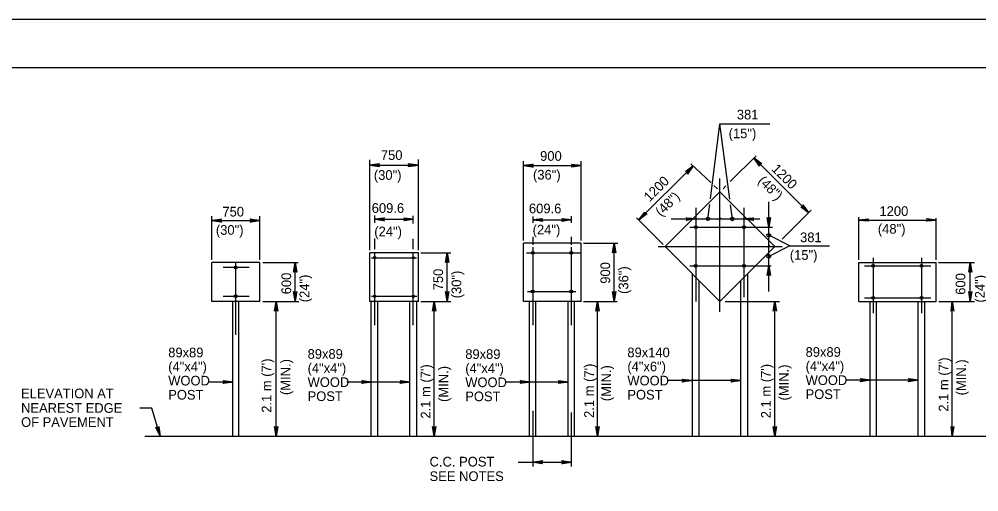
# Model space of a CAD drawing. Extents: x 649454 to 651200, y 295188 to 295782.
# Drawn here: x 649864.6 to 650161.4, y 295635.3 to 295781.6 of the extents above; entities that cross this region are included whole.
import ezdxf

# ---------------------------------------------------------------- set-up
doc = ezdxf.new("R2010")
doc.units = 0
for name, color, linetype in [('1', 7, 'Continuous'), ('2', 7, 'Continuous'), ('3', 7, 'Continuous'), ('PLT-BNDY', 7, 'Continuous')]:
    doc.layers.add(name, color=color, linetype=linetype)

msp = doc.modelspace()

# ---------------------------------------------------------------- linework, layer by layer
at = {"layer": '1'}
msp.add_line((649494.31, 295766.63), (650280.31, 295766.63), dxfattribs=at)
at = {"layer": '2'}
for p, q in [((650078.41, 295726.02), (650081.31, 295749.2)), ((650081.31, 295749.2), (650096.78, 295749.2)), ((649973.06, 295710.12), (649973.06, 295738.04)), ((649988.06, 295710.12), (649988.06, 295738.17)), ((650020.56, 295713.12), (650020.56, 295737.65)), ((650038.44, 295713.12), (650038.44, 295737.65)), ((650092.54, 295739.36), (650084.5, 295731.31)), ((650108.71, 295721.77), (650091.84, 295738.65)), ((649973.06, 295736.42), (649988.06, 295736.42)), ((650020.56, 295736.27), (650038.44, 295736.27)), ((650056.21, 295719.47), (650073.04, 295736.17)), ((650072.33, 295736.88), (650078.54, 295731.03)), ((650081.31, 295691), (650081.31, 295732.31)), ((650079.5, 295730.12), (650080.56, 295729.12)), ((650083.2, 295730.01), (650082.31, 295729.12)), ((650064.44, 295711.25), (650081.31, 295728.12)), ((650098.31, 295711.25), (650081.31, 295728.12)), ((650073.94, 295694.25), (650073.94, 295723.25)), ((650077.64, 295719.81), (650078.19, 295724.23)), ((650088.81, 295695.5), (650088.81, 295723.25)), ((650096.44, 295711.07), (650096.44, 295725.05)), ((649924.19, 295707.12), (649924.19, 295720.64)), ((649939.06, 295707.12), (649939.06, 295720.64)), ((649974.56, 295718.59), (649974.56, 295720.84)), ((649986.44, 295718.37), (649986.44, 295720.77)), ((650023.56, 295718.59), (650023.56, 295720.51)), ((650035.44, 295718.59), (650035.44, 295720.64)), ((650063.81, 295711.87), (650055.55, 295720.13)), ((650081.06, 295719.37), (650081.69, 295720.12)), ((650109.55, 295722.52), (650100.57, 295713.54)), ((650124.31, 295707.12), (650124.31, 295720.3)), ((650148.19, 295707.12), (650148.19, 295720.05)), ((649924.19, 295719.27), (649939.06, 295719.27)), ((649974.56, 295719.65), (649986.44, 295719.65)), ((650023.56, 295719.51), (650035.44, 295719.51)), ((650066.22, 295719.75), (650081.31, 295719.75)), ((650072.06, 295717.25), (650097.56, 295717.25)), ((650081.31, 295719.75), (650093.7, 295719.75)), ((650124.31, 295719.42), (650148.19, 295719.42)), ((650023.56, 295711.75), (650023.56, 295714.2)), ((650035.44, 295711.75), (650035.44, 295714.2)), ((650103.01, 295711.43), (650096.44, 295714.7)), ((649974.56, 295710.37), (649974.56, 295713.75)), ((649986.44, 295710.37), (649986.44, 295713.64)), ((650020.56, 295694.25), (650020.56, 295712.25)), ((650038.44, 295712.25), (650020.56, 295712.25)), ((650023.56, 295686.87), (650023.56, 295711)), ((650035.44, 295686.87), (650035.44, 295711)), ((650038.44, 295694.25), (650038.44, 295712.25)), ((650039.19, 295712.25), (650049.72, 295712.25)), ((650048.59, 295694.25), (650048.59, 295712.25)), ((650062.19, 295711.25), (650100.56, 295711.25)), ((650081.31, 295694.25), (650064.44, 295711.25)), ((650081.31, 295694.25), (650098.31, 295711.25)), ((650096.11, 295710.97), (650096.86, 295711.59)), ((650103.01, 295711.43), (650096.44, 295708.18)), ((650096.44, 295697.3), (650096.44, 295711.07)), ((650103.01, 295711.43), (650115.25, 295711.43)), ((649973.06, 295694.25), (649973.06, 295709.25)), ((649988.06, 295709.25), (649973.06, 295709.25)), ((649974.56, 295686.87), (649974.56, 295709.5)), ((649986.44, 295686.87), (649986.44, 295709.5)), ((649988.06, 295694.25), (649988.06, 295709.25)), ((649988.81, 295709.25), (649998.09, 295709.25)), ((649996.96, 295694.25), (649996.96, 295709.25)), ((650021.56, 295709.25), (650038.06, 295709.25)), ((650023.44, 295709.25), (650023.44, 295709.25)), ((650035.44, 295709.25), (650035.44, 295709.25)), ((649924.19, 295694.25), (649924.19, 295706.25)), ((649939.06, 295706.25), (649924.19, 295706.25)), ((649931.56, 295683.87), (649931.56, 295706.5)), ((649939.06, 295694.25), (649939.06, 295706.25)), ((649939.94, 295706.25), (649950.91, 295706.25)), ((649949.97, 295694.25), (649949.97, 295706.25)), ((649973.56, 295707.75), (649987.44, 295707.75)), ((649974.56, 295707.75), (649974.56, 295707.75)), ((649986.44, 295707.75), (649986.44, 295707.75)), ((650072.06, 295705.25), (650097.23, 295705.25)), ((650124.31, 295694.25), (650124.31, 295706.25)), ((650124.31, 295706.25), (650148.19, 295706.25)), ((650126.06, 295705.25), (650146.56, 295705.25)), ((650128.81, 295690.62), (650128.81, 295707.75)), ((650128.81, 295705.25), (650128.81, 295705.25)), ((650143.81, 295690.62), (650143.81, 295707.75)), ((650143.81, 295705.25), (650143.81, 295705.25)), ((650148.19, 295694.25), (650148.19, 295706.25)), ((650148.94, 295706.25), (650160.08, 295706.25)), ((650149.06, 295706.25), (650154.31, 295706.25)), ((650158.72, 295694.25), (650158.72, 295706.25)), ((649927.69, 295704.87), (649935.69, 295704.87)), ((649931.56, 295704.87), (649931.56, 295704.87)), ((650072.81, 295652.5), (650072.81, 295702.75)), ((650089.94, 295652.5), (650089.94, 295702.75)), ((650074.94, 295652.5), (650074.94, 295700.75)), ((650087.81, 295652.5), (650087.81, 295700.75)), ((650021.81, 295697.25), (650036.81, 295697.25)), ((650022.81, 295697.25), (650022.81, 295697.25)), ((650035.31, 295697.25), (650035.31, 295697.25)), ((649939.06, 295694.25), (649924.19, 295694.25)), ((649927.69, 295695.87), (649935.69, 295695.87)), ((649930.69, 295652.5), (649930.69, 295694.25)), ((649931.56, 295695.87), (649931.56, 295695.87)), ((649932.56, 295652.5), (649932.56, 295694.25)), ((649939.94, 295694.25), (649951.1, 295694.25)), ((649944.06, 295652.5), (649944.06, 295694.25)), ((649988.06, 295694.25), (649973.06, 295694.25)), ((649973.44, 295652.5), (649973.44, 295694.25)), ((649973.56, 295695.87), (649987.56, 295695.87)), ((649974.56, 295695.87), (649974.56, 295695.87)), ((649975.56, 295652.5), (649975.56, 295694.25)), ((649985.44, 295652.5), (649985.44, 295694.25)), ((649986.44, 295695.87), (649986.44, 295695.87)), ((649987.56, 295652.5), (649987.56, 295694.25)), ((649988.81, 295694.25), (649998.09, 295694.25)), ((649992.94, 295652.5), (649992.94, 295694.25)), ((650038.44, 295694.25), (650020.56, 295694.25)), ((650022.44, 295652.5), (650022.44, 295694.25)), ((650024.44, 295652.5), (650024.44, 295694.25)), ((650034.44, 295652.5), (650034.44, 295694.25)), ((650036.31, 295652.5), (650036.31, 295694.25)), ((650039.19, 295694.25), (650049.59, 295694.25)), ((650043.44, 295652.5), (650043.44, 295694.25)), ((650082.94, 295694.25), (650099.81, 295694.25)), ((650098.31, 295652.5), (650098.31, 295694.25)), ((650124.31, 295694.25), (650148.19, 295694.25)), ((650126.06, 295695.37), (650146.56, 295695.37)), ((650127.81, 295652.5), (650127.81, 295694.25)), ((650128.81, 295695.37), (650128.81, 295695.37)), ((650129.81, 295652.5), (650129.81, 295694.25)), ((650142.69, 295652.5), (650142.69, 295694.25)), ((650143.81, 295695.37), (650143.81, 295695.37)), ((650144.69, 295652.5), (650144.69, 295694.25)), ((650149.06, 295694.25), (650160.08, 295694.25)), ((650153.19, 295652.5), (650153.19, 295694.25)), ((650087.81, 295669.7), (650065.01, 295669.7)), ((650142.69, 295669.85), (650120.14, 295669.85)), ((649930.69, 295669.27), (649923.01, 295669.27)), ((649985.44, 295669.27), (649965.93, 295669.27)), ((650034.44, 295669.27), (650014.93, 295669.27)), ((649905.64, 295661.21), (649901.94, 295661.21)), ((649908.19, 295652.5), (649905.64, 295661.21)), ((650023.56, 295643.06), (650023.56, 295660.37)), ((650035.44, 295643.06), (650035.44, 295659.87)), ((649903.44, 295652.5), (650272.04, 295652.5)), ((650018.94, 295644.43), (650035.44, 295644.43))]:
    msp.add_line(p, q, dxfattribs=at)
for points in [[(650084.37, 295725.93), (650081.31, 295749.2)], [(650093.59, 295736.4), (650093.71, 295736.65), (650091.84, 295738.65), (650093.59, 295736.4), (650093.59, 295736.15), (650091.84, 295738.65), (650093.84, 295736.77), (650094.09, 295736.9), (650091.84, 295738.65), (650094.34, 295736.9), (650094.09, 295736.9)], [(649975.94, 295736.04), (649975.81, 295736.29), (649973.06, 295736.42), (649975.94, 295736.04), (649976.06, 295735.92), (649973.06, 295736.42), (649975.81, 295736.54), (649975.94, 295736.79), (649973.06, 295736.42), (649976.06, 295736.92), (649975.94, 295736.79)], [(649985.06, 295736.79), (649985.19, 295736.54), (649988.06, 295736.42), (649985.06, 295736.79), (649985.06, 295736.92), (649988.06, 295736.42), (649985.19, 295736.29), (649985.06, 295736.04), (649988.06, 295736.42), (649985.06, 295735.92), (649985.06, 295736.04)], [(650023.31, 295735.9), (650023.19, 295736.15), (650020.56, 295736.27), (650023.31, 295735.9), (650023.56, 295735.77), (650020.56, 295736.27), (650023.19, 295736.4), (650023.31, 295736.65), (650020.56, 295736.27), (650023.56, 295736.77), (650023.31, 295736.65)], [(650035.56, 295736.65), (650035.69, 295736.4), (650038.44, 295736.27), (650035.56, 295736.65), (650035.44, 295736.77), (650038.44, 295736.27), (650035.69, 295736.15), (650035.56, 295735.9), (650038.44, 295736.27), (650035.44, 295735.77), (650035.56, 295735.9)], [(650070.79, 295734.42), (650070.91, 295734.42), (650073.04, 295736.17), (650070.79, 295734.42), (650070.66, 295734.42), (650073.04, 295736.17), (650071.16, 295734.17), (650071.29, 295733.92), (650073.04, 295736.17), (650071.29, 295733.67), (650071.29, 295733.92)], [(650085.19, 295719.75), (650084.61, 295724.1)], [(650107.09, 295723.9), (650106.96, 295723.77), (650108.71, 295721.77), (650107.09, 295723.9), (650106.96, 295724.15), (650108.71, 295721.77), (650106.71, 295723.52), (650106.59, 295723.4), (650108.71, 295721.77), (650106.34, 295723.4), (650106.59, 295723.4)], [(649977.31, 295719.27), (649977.31, 295719.52), (649974.56, 295719.65), (649977.31, 295719.27), (649977.56, 295719.15), (649974.56, 295719.65), (649977.31, 295719.77), (649977.31, 295720.02), (649974.56, 295719.65), (649977.56, 295720.15), (649977.31, 295720.02)], [(649983.69, 295720.02), (649983.81, 295719.77), (649986.44, 295719.65), (649983.69, 295720.02), (649983.56, 295720.15), (649986.44, 295719.65), (649983.81, 295719.52), (649983.69, 295719.27), (649986.44, 295719.65), (649983.56, 295719.15), (649983.69, 295719.27)], [(650026.31, 295719.14), (650026.19, 295719.39), (650023.56, 295719.51), (650026.31, 295719.14), (650026.44, 295719.01), (650023.56, 295719.51), (650026.19, 295719.51), (650026.31, 295719.76), (650023.56, 295719.51), (650026.44, 295719.89), (650026.31, 295719.76)], [(650032.56, 295719.76), (650032.69, 295719.64), (650035.44, 295719.51), (650032.56, 295719.76), (650032.44, 295719.89), (650035.44, 295719.51), (650032.69, 295719.39), (650032.69, 295719.26), (650035.44, 295719.51), (650032.44, 295719.01), (650032.69, 295719.26)], [(650058.59, 295721.35), (650058.34, 295721.35), (650056.21, 295719.47), (650058.59, 295721.35), (650058.84, 295721.35), (650056.21, 295719.47), (650058.21, 295721.47), (650058.09, 295721.72), (650056.21, 295719.47), (650058.09, 295721.85), (650058.09, 295721.72)], [(650071.06, 295720), (650071.19, 295719.87), (650073.94, 295719.75), (650071.06, 295720), (650070.94, 295720.12), (650073.94, 295719.75), (650071.19, 295719.62), (650071.19, 295719.5), (650073.94, 295719.75), (650070.94, 295719.25), (650071.19, 295719.5)], [(650091.56, 295719.37), (650091.44, 295719.62), (650088.81, 295719.75), (650091.56, 295719.37), (650091.69, 295719.25), (650088.81, 295719.75), (650091.44, 295719.75), (650091.56, 295720), (650088.81, 295719.75), (650091.69, 295720.12), (650091.56, 295720)], [(650096.82, 295720.12), (650096.57, 295720), (650096.44, 295717.25), (650096.82, 295720.12), (650096.94, 295720.25), (650096.44, 295717.25), (650096.19, 295720), (650096.07, 295720.12), (650096.44, 295717.25), (650095.94, 295720.25), (650096.07, 295720.12)], [(650145.31, 295719.8), (650145.44, 295719.55), (650148.19, 295719.42), (650145.31, 295719.8), (650145.19, 295719.92), (650148.19, 295719.42), (650145.44, 295719.3), (650145.44, 295719.17), (650148.19, 295719.42), (650145.19, 295719.05), (650145.44, 295719.17)], [(649926.94, 295718.89), (649926.81, 295719.14), (649924.19, 295719.27), (649926.94, 295718.89), (649927.19, 295718.77), (649924.19, 295719.27), (649926.81, 295719.39), (649926.94, 295719.64), (649924.19, 295719.27), (649927.19, 295719.77), (649926.94, 295719.64)], [(649936.19, 295719.64), (649936.31, 295719.39), (649939.06, 295719.27), (649936.19, 295719.64), (649936.06, 295719.77), (649939.06, 295719.27), (649936.31, 295719.14), (649936.31, 295718.89), (649939.06, 295719.27), (649936.06, 295718.77), (649936.31, 295718.89)], [(650127.19, 295719.17), (650127.06, 295719.3), (650124.31, 295719.42), (650127.19, 295719.17), (650127.31, 295719.05), (650124.31, 295719.42), (650127.06, 295719.55), (650127.19, 295719.67), (650124.31, 295719.42), (650127.31, 295719.8), (650127.19, 295719.67)], [(650048.22, 295709.37), (650048.34, 295709.5), (650048.59, 295712.25), (650048.22, 295709.37), (650048.09, 295709.25), (650048.59, 295712.25), (650048.72, 295709.5), (650048.84, 295709.37), (650048.59, 295712.25), (650049.09, 295709.25), (650048.84, 295709.37)], [(649996.59, 295706.37), (649996.84, 295706.5), (649996.96, 295709.25), (649996.59, 295706.37), (649996.46, 295706.25), (649996.96, 295709.25), (649997.21, 295706.5), (649997.34, 295706.37), (649996.96, 295709.25), (649997.46, 295706.25), (649997.34, 295706.37)], [(649949.6, 295703.37), (649949.72, 295703.5), (649949.97, 295706.25), (649949.6, 295703.37), (649949.47, 295703.25), (649949.97, 295706.25), (649950.1, 295703.5), (649950.22, 295703.37), (649949.97, 295706.25), (649950.47, 295703.25), (649950.22, 295703.37)], [(650096.07, 295702.37), (650096.19, 295702.5), (650096.44, 295705.25), (650096.07, 295702.37), (650095.94, 295702.25), (650096.44, 295705.25), (650096.57, 295702.5), (650096.69, 295702.37), (650096.44, 295705.25), (650096.94, 295702.25), (650096.69, 295702.37)], [(650158.47, 295703.37), (650158.59, 295703.5), (650158.72, 295706.25), (650158.47, 295703.37), (650158.34, 295703.25), (650158.72, 295706.25), (650158.84, 295703.5), (650159.09, 295703.37), (650158.72, 295706.25), (650159.22, 295703.25), (650159.09, 295703.37)], [(649950.35, 295697.12), (649950.1, 295697), (649949.97, 295694.25), (649950.35, 295697.12), (649950.47, 295697.25), (649949.97, 295694.25), (649949.85, 295697), (649949.6, 295697.12), (649949.97, 295694.25), (649949.47, 295697.25), (649949.6, 295697.12)], [(649997.34, 295697.12), (649997.21, 295697), (649996.96, 295694.25), (649997.34, 295697.12), (649997.46, 295697.25), (649996.96, 295694.25), (649996.84, 295697), (649996.71, 295697.12), (649996.96, 295694.25), (649996.46, 295697.25), (649996.71, 295697.12)], [(650048.97, 295697.12), (650048.72, 295697), (650048.59, 295694.25), (650048.97, 295697.12), (650049.09, 295697.25), (650048.59, 295694.25), (650048.34, 295697), (650048.22, 295697.12), (650048.59, 295694.25), (650048.09, 295697.25), (650048.22, 295697.12)], [(650159.09, 295697.12), (650158.84, 295697), (650158.72, 295694.25), (650159.09, 295697.12), (650159.22, 295697.25), (650158.72, 295694.25), (650158.59, 295697), (650158.47, 295697.12), (650158.72, 295694.25), (650158.34, 295697.25), (650158.47, 295697.12)], [(649943.69, 295691.5), (649943.81, 295691.62), (649944.06, 295694.25), (649943.69, 295691.5), (649943.56, 295691.25), (649944.06, 295694.25), (649944.19, 295691.62), (649944.31, 295691.5), (649944.06, 295694.25), (649944.56, 295691.25), (649944.31, 295691.5)], [(649992.56, 295691.5), (649992.81, 295691.62), (649992.94, 295694.25), (649992.56, 295691.5), (649992.44, 295691.25), (649992.94, 295694.25), (649993.19, 295691.62), (649993.31, 295691.5), (649992.94, 295694.25), (649993.44, 295691.25), (649993.31, 295691.5)], [(650043.06, 295691.5), (650043.19, 295691.62), (650043.44, 295694.25), (650043.06, 295691.5), (650042.94, 295691.25), (650043.44, 295694.25), (650043.56, 295691.62), (650043.69, 295691.5), (650043.44, 295694.25), (650043.94, 295691.25), (650043.69, 295691.5)], [(650097.94, 295691.5), (650098.19, 295691.62), (650098.31, 295694.25), (650097.94, 295691.5), (650097.81, 295691.25), (650098.31, 295694.25), (650098.44, 295691.62), (650098.69, 295691.5), (650098.31, 295694.25), (650098.81, 295691.25), (650098.69, 295691.5)], [(650152.94, 295691.5), (650153.06, 295691.62), (650153.19, 295694.25), (650152.94, 295691.5), (650152.81, 295691.25), (650153.19, 295694.25), (650153.31, 295691.62), (650153.56, 295691.5), (650153.19, 295694.25), (650153.69, 295691.25), (650153.56, 295691.5)], [(649927.81, 295669.64), (649927.94, 295669.52), (649930.69, 295669.27), (649927.81, 295669.64), (649927.69, 295669.77), (649930.69, 295669.27), (649927.94, 295669.14), (649927.81, 295669.02), (649930.69, 295669.27), (649927.69, 295668.77), (649927.81, 295669.02)], [(649970.73, 295669.64), (649970.85, 295669.52), (649973.6, 295669.27), (649970.73, 295669.64), (649970.6, 295669.77), (649973.6, 295669.27), (649970.85, 295669.14), (649970.73, 295669.02), (649973.6, 295669.27), (649970.6, 295668.77), (649970.73, 295669.02)], [(649982.56, 295669.64), (649982.69, 295669.52), (649985.44, 295669.27), (649982.56, 295669.64), (649982.44, 295669.77), (649985.44, 295669.27), (649982.69, 295669.14), (649982.56, 295669.02), (649985.44, 295669.27), (649982.44, 295668.77), (649982.56, 295669.02)], [(650019.73, 295669.64), (650019.85, 295669.52), (650022.6, 295669.27), (650019.73, 295669.64), (650019.6, 295669.77), (650022.6, 295669.27), (650019.85, 295669.14), (650019.73, 295669.02), (650022.6, 295669.27), (650019.6, 295668.77), (650019.73, 295669.02)], [(650031.56, 295669.64), (650031.69, 295669.52), (650034.44, 295669.27), (650031.56, 295669.64), (650031.44, 295669.77), (650034.44, 295669.27), (650031.69, 295669.14), (650031.56, 295669.02), (650034.44, 295669.27), (650031.44, 295668.77), (650031.56, 295669.02)], [(650069.8, 295670.07), (650069.93, 295669.95), (650072.68, 295669.7), (650069.8, 295670.07), (650069.68, 295670.2), (650072.68, 295669.7), (650069.93, 295669.57), (650069.8, 295669.45), (650072.68, 295669.7), (650069.68, 295669.2), (650069.8, 295669.45)], [(650084.94, 295670.07), (650085.06, 295669.95), (650087.81, 295669.7), (650084.94, 295670.07), (650084.81, 295670.2), (650087.81, 295669.7), (650085.06, 295669.57), (650084.94, 295669.45), (650087.81, 295669.7), (650084.81, 295669.2), (650084.94, 295669.45)], [(650124.94, 295670.23), (650125.07, 295670.1), (650127.82, 295669.85), (650124.94, 295670.23), (650124.82, 295670.35), (650127.82, 295669.85), (650125.07, 295669.73), (650124.94, 295669.6), (650127.82, 295669.85), (650124.82, 295669.35), (650124.94, 295669.6)], [(650139.81, 295670.23), (650139.94, 295670.1), (650142.69, 295669.85), (650139.81, 295670.23), (650139.69, 295670.35), (650142.69, 295669.85), (650139.94, 295669.73), (650139.81, 295669.6), (650142.69, 295669.85), (650139.69, 295669.35), (650139.81, 295669.6)], [(649907.78, 295655.24), (649907.58, 295655.05), (649908.19, 295652.5), (649907.78, 295655.24), (649907.83, 295655.52), (649908.19, 295652.5), (649907.34, 295654.98), (649907.06, 295655.04), (649908.19, 295652.5), (649906.87, 295655.24), (649907.06, 295655.04)], [(649944.44, 295655.25), (649944.19, 295655.12), (649944.06, 295652.5), (649944.44, 295655.25), (649944.56, 295655.5), (649944.06, 295652.5), (649943.94, 295655.12), (649943.69, 295655.25), (649944.06, 295652.5), (649943.56, 295655.5), (649943.69, 295655.25)], [(649993.31, 295655.25), (649993.19, 295655.12), (649992.94, 295652.5), (649993.31, 295655.25), (649993.44, 295655.5), (649992.94, 295652.5), (649992.81, 295655.12), (649992.69, 295655.25), (649992.94, 295652.5), (649992.44, 295655.5), (649992.69, 295655.25)], [(650043.81, 295655.25), (650043.56, 295655.12), (650043.44, 295652.5), (650043.81, 295655.25), (650043.94, 295655.5), (650043.44, 295652.5), (650043.19, 295655.12), (650043.06, 295655.25), (650043.44, 295652.5), (650042.94, 295655.5), (650043.06, 295655.25)], [(650098.69, 295655.25), (650098.44, 295655.12), (650098.31, 295652.5), (650098.69, 295655.25), (650098.81, 295655.5), (650098.31, 295652.5), (650098.19, 295655.12), (650097.94, 295655.25), (650098.31, 295652.5), (650097.81, 295655.5), (650097.94, 295655.25)], [(650153.56, 295655.25), (650153.31, 295655.12), (650153.19, 295652.5), (650153.56, 295655.25), (650153.69, 295655.5), (650153.19, 295652.5), (650153.06, 295655.12), (650152.94, 295655.25), (650153.19, 295652.5), (650152.81, 295655.5), (650152.94, 295655.25)], [(650026.31, 295644.06), (650026.19, 295644.18), (650023.56, 295644.43), (650026.31, 295644.06), (650026.44, 295643.93), (650023.56, 295644.43), (650026.19, 295644.56), (650026.31, 295644.81), (650023.56, 295644.43), (650026.44, 295644.93), (650026.31, 295644.81)], [(650032.56, 295644.81), (650032.69, 295644.56), (650035.44, 295644.43), (650032.56, 295644.81), (650032.44, 295644.93), (650035.44, 295644.43), (650032.69, 295644.31), (650032.69, 295644.06), (650035.44, 295644.43), (650032.44, 295643.93), (650032.69, 295644.06)]]:
    msp.add_lwpolyline(points, dxfattribs=at)
for centre, radius in [((650077.64, 295719.81), 0.55), ((650085.19, 295719.75), 0.55), ((650073.89, 295717.21), 0.441), ((650088.81, 295717.19), 0.441), ((650096.44, 295714.7), 0.55), ((649974.52, 295707.76), 0.331), ((649986.5, 295707.75), 0.331), ((650023.45, 295709.26), 0.441), ((650035.38, 295709.28), 0.441), ((650096.44, 295708.18), 0.55), ((649931.58, 295704.78), 0.441), ((650073.86, 295705.22), 0.441), ((650088.81, 295705.26), 0.441), ((650128.75, 295705.23), 0.441), ((650143.68, 295705.28), 0.441), ((649931.58, 295695.81), 0.441), ((649974.53, 295695.8), 0.331), ((649986.5, 295695.8), 0.331), ((650023.44, 295697.32), 0.441), ((650035.38, 295697.3), 0.441), ((650128.75, 295695.32), 0.441), ((650143.67, 295695.29), 0.441)]:
    msp.add_circle(centre, radius, dxfattribs=at)
at = {"layer": '3'}
for p, q in [((650073.94, 295717.25), (650073.94, 295717.25)), ((650088.81, 295717.25), (650088.81, 295717.25)), ((650073.94, 295705.25), (650073.94, 295705.25)), ((650088.81, 295705.25), (650088.81, 295705.25))]:
    msp.add_line(p, q, dxfattribs=at)
at = {"layer": 'PLT-BNDY'}
msp.add_lwpolyline([(649454.31, 295781.63), (650295.31, 295781.63), (650295.31, 295187.63), (649454.31, 295187.63)], close=True, dxfattribs=at)

# ---------------------------------------------------------------- texts
at = {"layer": '3'}
for s, height, p in [('381', 3, (650086.56, 295750.59)), ('(15")', 3, (650084.03, 295744.77)), ('750', 3, (649976.46, 295738.04)), ('900', 3, (650025.72, 295737.77)), ('(30")', 3, (649974.29, 295731.87)), ('(36")', 3, (650023.52, 295731.96)), ('750', 3, (649927.44, 295720.52)), ('609.6', 3, (649973.63, 295721.64)), ('609.6', 3, (650022.26, 295721.52)), ('1200', 3, (650130.68, 295720.7)), ('(30")', 3, (649925.43, 295714.86)), ('(24")', 3, (649974.43, 295714.39)), ('(24")', 3, (650023.41, 295714.95)), ('(48")', 3, (650130.18, 295715.2)), ('381', 3, (650106.13, 295712.57)), ('(15")', 3, (650102.95, 295707.11)), ('89x89', 2.988, (649910.7, 295676.92)), ('89x89', 2.988, (649953.81, 295676.47)), ('89x89', 2.988, (650002.57, 295676.42)), ('89x140', 2.988, (650052.71, 295676.94)), ('89x89', 2.988, (650107.84, 295677.08)), ('(4"x4")', 2.988, (649910.7, 295672.56)), ('(4"x6")', 2.988, (650052.71, 295672.58)), ('(4"x4")', 2.988, (650107.84, 295672.71)), ('(4"x4")', 2.988, (649953.81, 295672.1)), ('(4"x4")', 2.988, (650002.57, 295672.05)), ('WOOD', 2.988, (649910.7, 295668.2)), ('WOOD', 2.988, (649953.81, 295667.74)), ('WOOD', 2.988, (650002.57, 295667.69)), ('WOOD', 2.988, (650052.71, 295668.22)), ('WOOD', 2.988, (650107.84, 295668.35)), ('ELEVATION AT', 2.988, (649865.19, 295664.24)), ('POST', 2.988, (649910.7, 295663.83)), ('POST', 2.988, (649953.81, 295663.38)), ('POST', 2.988, (650052.71, 295663.85)), ('POST', 2.988, (650107.84, 295663.99)), ('POST', 2.988, (650002.57, 295663.33)), ('NEAREST EDGE', 2.988, (649865.19, 295659.74)), ('OF PAVEMENT', 2.988, (649865.19, 295655.37)), ('C.C. POST', 3, (649991.52, 295643.11)), ('SEE NOTES', 3, (649991.52, 295638.61))]:
    msp.add_text(s, height=height, dxfattribs=at).set_placement(p)
for s, rotation, p in [('1200', 315, (650097.09, 295735.02)), ('1200', 45, (650059.58, 295724.89)), ('(48")', 315, (650092.91, 295731.33)), ('(48")', 45, (650063.14, 295720.35)), ('900', 90, (650047.38, 295699.7)), ('600', 90, (649948.72, 295696.43)), ('(24")', 90, (649954.31, 295693.98)), ('750', 90, (649995.7, 295697.67)), ('(30")', 90, (650001.33, 295695.19)), ('(36")', 90, (650053, 295696.55)), ('600', 90, (650157.24, 295696.29)), ('(24")', 90, (650163.24, 295693.87)), ("2.1 m (7') ", 90, (649942.61, 295659.74)), ('(MIN.)', 90, (649948.47, 295665.24)), ("2.1 m (7') ", 90, (650152.01, 295660.08)), ('(MIN.)', 90, (650157.42, 295665.13)), ("2.1 m (7') ", 90, (649991.81, 295657.94)), ('(MIN.)', 90, (649997.33, 295663.1)), ("2.1 m (7') ", 90, (650042.36, 295658.16)), ('(MIN.)', 90, (650047.65, 295663.33)), ("2.1 m (7') ", 90, (650097.07, 295658.05)), ('(MIN.)', 90, (650102.59, 295663.55))]:
    msp.add_text(s, height=3, rotation=rotation, dxfattribs=at).set_placement(p)

doc.saveas('drawing.dxf')
